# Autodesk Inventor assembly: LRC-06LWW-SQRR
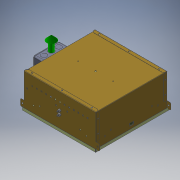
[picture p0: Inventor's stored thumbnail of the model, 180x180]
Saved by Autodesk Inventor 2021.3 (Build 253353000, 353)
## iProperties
Part Number: LRC-06LWW-SQRR
Document SubType Name: Assembly
Designer: JChurch
description: 0:0:Lensed 6" Wall Wash - COB LED
manufacturer: 0:0:The Kirlin Company
model: 0:0:LRC-06LWW
url: 0:0:
load_classification: Lighting
motor: 0 ul
Author: JChurch
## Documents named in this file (6)
- X:\Revit Files\0000-Un-Zipped\COB\LRC-06LWW-SQR\LRC-06LWW-SQRR.iam
- X:\INVENTOR\830\830376-00-00.iam
- X:\INVENTOR\881\881088-00-00.iam
- X:\INVENTOR\700\700466-25-XX (NEW).iam
- X:\INVENTOR\725\725267-00-00.ipt
- X:\Revit Files\0000-Un-Zipped\COB\LRC-06LWW-SQR\LRC-06LWW-SQRR_Substitute_1.ipt
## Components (5 placed, 5 different names)
1. 830376-00-00:1 [sub-assembly] — Mate:1, Mate:2, Flush:1, Tangent:1, Angle:1, Mate:5
2. 881088-00-00:1 [sub-assembly] — Mate:3, Tangent:1, Angle:1
3. 700466-25-XX (NEW):1 [sub-assembly] — Mate:4, Flush:2, Mate:5, Mate:6, Mate:7, Mate:8
4. 725267-00-00:1 — Mate:6, Mate:7, Mate:8
5. LRC-06LWW-SQRR_Substitute_1:1
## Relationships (12: Mate 8, Flush 2, Tangent 1, Angle 1)
- Mate:1: 830376-00-00:1
- Mate:2: 830376-00-00:1
- Flush:1: 830376-00-00:1
- Mate:3: 881088-00-00:1
- Tangent:1: 830376-00-00:1 ↔ 881088-00-00:1
- Angle:1: 830376-00-00:1 ↔ 881088-00-00:1
- Mate:4: 700466-25-XX (NEW):1
- Flush:2: 700466-25-XX (NEW):1
- Mate:5: 830376-00-00:1 ↔ 700466-25-XX (NEW):1
- Mate:6: 700466-25-XX (NEW):1 ↔ 725267-00-00:1
- Mate:7: 700466-25-XX (NEW):1 ↔ 725267-00-00:1
- Mate:8: 700466-25-XX (NEW):1 ↔ 725267-00-00:1
